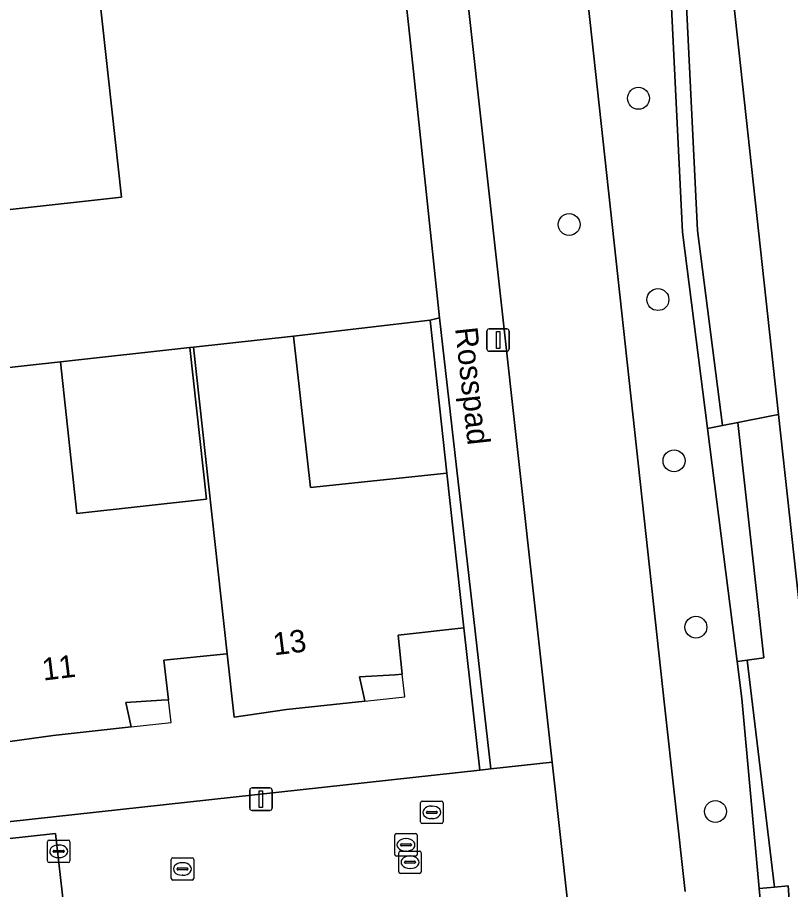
# Model space of a CAD drawing. Extents: x 161248 to 161848, y 384871 to 385383.
# Drawn here: x 161394.3 to 161428.75, y 385160.46 to 385199.35 of the extents above; entities that cross this region are included whole.
import ezdxf

# ---------------------------------------------------------------- set-up
doc = ezdxf.new("R2010")
doc.units = 0
for name, color, linetype in [('IMGEO_Boom', 7, 'Continuous'), ('IMGEO_Erf', 7, 'Continuous'), ('IMGEO_Groenvoorziening', 7, 'Continuous'), ('IMGEO_Hek', 7, 'Continuous'), ('IMGEO_Kolk', 7, 'Continuous'), ('IMGEO_Lichtmast', 7, 'Continuous'), ('IMGEO_Muur', 7, 'Continuous'), ('IMGEO_Openbare_ruimte_label', 7, 'Continuous'), ('IMGEO_Pand', 7, 'Continuous'), ('IMGEO_Pand_nummerreeks', 7, 'Continuous'), ('IMGEO_Pand_overbouw', 7, 'Continuous'), ('IMGEO_Rijbaan_lokaal_open', 7, 'Continuous'), ('IMGEO_Rioolput', 7, 'Continuous'), ('IMGEO_Voetpad_gesloten', 7, 'Continuous'), ('IMGEO_Voetpad_open', 7, 'Continuous')]:
    doc.layers.add(name, color=color, linetype=linetype)

msp = doc.modelspace()

# ---------------------------------------------------------------- linework, layer by layer
at = {"layer": 'IMGEO_Boom'}
for centre in [(161421.968, 385195.743), (161418.879, 385190.113), (161422.835, 385186.767), (161423.555, 385179.578), (161424.528, 385172.161), (161425.399, 385163.944)]:
    msp.add_circle(centre, 0.489, dxfattribs=at)
at = {"layer": 'IMGEO_Erf'}
for points in [[(161391.744, 385183.5), (161396.212, 385183.986), (161401.98, 385184.625), (161402.139, 385184.643), (161406.592, 385185.134), (161412.682, 385185.849), (161413.106, 385185.96), (161411.781, 385198.48), (161406.165, 385250), (161400.82, 385299.379)], [(161389.489, 385206.312), (161397.217, 385207.042), (161398.94, 385191.336), (161393.97, 385190.79)], [(161341.751, 385157.774), (161414.901, 385165.791), (161414.193, 385172.128), (161411.258, 385171.8), (161411.446, 385170.059), (161411.127, 385170.038), (161409.532, 385169.942), (161409.773, 385168.87), (161409.775, 385168.859), (161406.289, 385168.487), (161403.948, 385168.141), (161403.638, 385170.967), (161403.479, 385170.951), (161400.824, 385170.684), (161401.024, 385168.918), (161400.714, 385168.901), (161399.123, 385168.803), (161399.358, 385167.712), (161395.885, 385167.336), (161393.526, 385167.003)]]:
    msp.add_lwpolyline(points, dxfattribs=at)
for points in [[(161413.425, 385179.033), (161412.682, 385185.849), (161406.592, 385185.134), (161407.352, 385178.387)], [(161401.98, 385184.625), (161396.212, 385183.986), (161396.948, 385177.226), (161402.725, 385177.866)]]:
    msp.add_lwpolyline(points, close=True, dxfattribs=at)
at = {"layer": 'IMGEO_Groenvoorziening'}
for points in [[(161410.885, 385280.109), (161414.256, 385250), (161418.32, 385212.789), (161419.633, 385200.77), (161423.135, 385168.705), (161424.044, 385160.38)], [(161428.423, 385148.652), (161427.348, 385160.513), (161426.581, 385168.985), (161426.371, 385170.626), (161425.044, 385181.025), (161423.927, 385189.776), (161423.301, 385202.539), (161422.5, 385209.799), (161420.12, 385231.368), (161419.414, 385237.765), (161418.8, 385243.335), (161418.558, 385245.528), (161418.304, 385247.831), (161417.932, 385251.204), (161416.631, 385262.992), (161416.555, 385263.685), (161415.768, 385270.902)], [(161424.044, 385160.38), (161423.135, 385168.705), (161419.633, 385200.77), (161414.353, 385200.201), (161418.12, 385166.146), (161426.978, 385086.052)]]:
    msp.add_lwpolyline(points, dxfattribs=at)
for points in [[(161422.5, 385209.799), (161423.301, 385202.539), (161423.927, 385189.776), (161425.044, 385181.025), (161425.711, 385181.155), (161424.602, 385189.844), (161423.976, 385202.607), (161423.18, 385209.868)], [(161426.369, 385198.57), (161425.115, 385210.061), (161424.841, 385210.036), (161423.691, 385209.92), (161423.18, 385209.868), (161423.976, 385202.607), (161424.602, 385189.844), (161425.711, 385181.155), (161426.394, 385181.289), (161427.894, 385181.581), (161428.216, 385181.647)], [(161428.216, 385181.647), (161427.894, 385181.581), (161426.394, 385181.289), (161427.562, 385170.797), (161426.819, 385170.69), (161428.029, 385160.572), (161428.642, 385160.625), (161429.639, 385147.11), (161428.645, 385146.959), (161429.316, 385141.851), (161430.492, 385141.951), (161432.485, 385123.048), (161434.155, 385123.24), (161434.587, 385123.289)], [(161425.044, 385181.025), (161426.371, 385170.626), (161426.819, 385170.69), (161427.562, 385170.797), (161426.394, 385181.289), (161425.711, 385181.155)], [(161428.029, 385160.572), (161426.819, 385170.69), (161426.371, 385170.626), (161426.581, 385168.985), (161427.348, 385160.513)], [(161427.348, 385160.513), (161428.423, 385148.652), (161428.645, 385146.959), (161429.639, 385147.11), (161428.642, 385160.625), (161428.029, 385160.572)]]:
    msp.add_lwpolyline(points, close=True, dxfattribs=at)
at = {"layer": 'IMGEO_Hek'}
for points in [[(161423.135, 385168.705), (161419.633, 385200.77)], [(161424.044, 385160.38), (161423.135, 385168.705)]]:
    msp.add_lwpolyline(points, dxfattribs=at)
at = {"layer": 'IMGEO_Kolk'}
for p, q in [((161411.108, 385162.028), (161411.108, 385162.88)), ((161411.183, 385162.954), (161412.035, 385162.954)), ((161411.596, 385162.734), (161411.621, 385162.734)), ((161412.109, 385162.88), (161412.109, 385162.028)), ((161411.367, 385162.448), (161411.367, 385162.46)), ((161411.805, 385162.411), (161411.407, 385162.411)), ((161411.41, 385162.497), (161411.808, 385162.497)), ((161411.851, 385162.46), (161411.851, 385162.448)), ((161401.223, 385161.881), (161402.075, 385161.881)), ((161412.035, 385161.954), (161411.183, 385161.954)), ((161411.619, 385162.174), (161411.594, 385162.174)), ((161401.148, 385160.955), (161401.148, 385161.807)), ((161401.636, 385161.661), (161401.661, 385161.661)), ((161402.149, 385161.807), (161402.149, 385160.955)), ((161401.407, 385161.375), (161401.407, 385161.387)), ((161401.845, 385161.338), (161401.447, 385161.338)), ((161401.45, 385161.424), (161401.848, 385161.424)), ((161401.891, 385161.387), (161401.891, 385161.375)), ((161402.075, 385160.881), (161401.223, 385160.881)), ((161401.659, 385161.101), (161401.634, 385161.101))]:
    msp.add_line(p, q, dxfattribs=at)
for points in [[(161411.108, 385162.028), (161411.108, 385162.88)], [(161411.183, 385162.954), (161412.035, 385162.954)], [(161412.109, 385162.88), (161412.109, 385162.028)], [(161401.223, 385161.881), (161402.075, 385161.881)], [(161412.035, 385161.954), (161411.183, 385161.954)], [(161401.148, 385160.955), (161401.148, 385161.807)], [(161402.149, 385161.807), (161402.149, 385160.955)], [(161402.075, 385160.881), (161401.223, 385160.881)]]:
    msp.add_lwpolyline(points, dxfattribs=at)
for centre, radius, start, end in [((161411.185, 385162.878), 0.0765, 91.552, 178.448), ((161411.185, 385162.878), 0.0765, 91.552, 178.448), ((161412.033, 385162.878), 0.0765, 1.552, 88.448), ((161412.033, 385162.878), 0.0765, 1.552, 88.448), ((161411.407, 385162.457), 0.0403, 85.8775, 175.7526), ((161411.404, 385162.447), 0.0366, 178.938, 274.7102), ((161411.808, 385162.454), 0.043, 264.8664, 352.4533), ((161411.812, 385162.459), 0.0386, 1.7309, 96.639), ((161401.225, 385161.805), 0.0765, 91.552, 178.448), ((161401.225, 385161.805), 0.0765, 91.552, 178.448), ((161402.073, 385161.805), 0.0765, 1.552, 88.448), ((161402.073, 385161.805), 0.0765, 1.552, 88.448), ((161411.185, 385162.03), 0.0765, 181.552, 268.448), ((161411.185, 385162.03), 0.0765, 181.552, 268.448), ((161412.033, 385162.03), 0.0765, 271.552, 358.448), ((161412.033, 385162.03), 0.0765, 271.552, 358.448), ((161401.447, 385161.384), 0.0403, 85.8775, 175.7526), ((161401.444, 385161.374), 0.0366, 178.938, 274.7102), ((161401.848, 385161.381), 0.043, 264.8664, 352.4533), ((161401.852, 385161.386), 0.0386, 1.7309, 96.639), ((161401.225, 385160.957), 0.0765, 181.552, 268.448), ((161401.225, 385160.957), 0.0765, 181.552, 268.448), ((161402.073, 385160.957), 0.0765, 271.552, 358.448), ((161402.073, 385160.957), 0.0765, 271.552, 358.448)]:
    msp.add_arc(centre, radius, start, end, dxfattribs=at)
for centre, major_axis, ratio, start_param, end_param in [((161411.595, 385162.454), (-0.387, 0.002), 0.722429, 4.712389, 7.853982), ((161411.62, 385162.454), (-0.39, 0.002), 0.717154, 1.570796, 4.712389), ((161401.635, 385161.381), (-0.387, 0.002), 0.722429, 4.712389, 7.853982), ((161401.66, 385161.381), (-0.39, 0.002), 0.717154, 1.570796, 4.712389)]:
    msp.add_ellipse(centre, major_axis=major_axis, ratio=ratio, start_param=start_param, end_param=end_param, dxfattribs=at)
at = {"layer": 'IMGEO_Lichtmast'}
for p, q in [((161415.217, 385184.563), (161415.217, 385185.363)), ((161415.217, 385185.363), (161415.217, 385184.563)), ((161415.317, 385185.463), (161416.107, 385185.463)), ((161416.107, 385185.463), (161415.317, 385185.463)), ((161416.207, 385185.363), (161416.207, 385184.563)), ((161416.207, 385184.563), (161416.207, 385185.363)), ((161416.107, 385184.463), (161415.317, 385184.463)), ((161415.317, 385184.463), (161416.107, 385184.463)), ((161404.75, 385164.992), (161405.54, 385164.992)), ((161405.54, 385164.992), (161404.75, 385164.992)), ((161404.65, 385164.092), (161404.65, 385164.892)), ((161404.65, 385164.892), (161404.65, 385164.092)), ((161405.64, 385164.892), (161405.64, 385164.092)), ((161405.64, 385164.092), (161405.64, 385164.892)), ((161405.54, 385163.992), (161404.75, 385163.992)), ((161404.75, 385163.992), (161405.54, 385163.992))]:
    msp.add_line(p, q, dxfattribs=at)
for points in [[(161415.637, 385185.338), (161415.787, 385185.338), (161415.787, 385184.588), (161415.637, 385184.588), (161415.637, 385185.338)], [(161405.07, 385164.867), (161405.22, 385164.867), (161405.22, 385164.117), (161405.07, 385164.117), (161405.07, 385164.867)]]:
    msp.add_lwpolyline(points, dxfattribs=at)
for centre, start, end in [((161415.317, 385185.363), 90, 180), ((161415.317, 385185.363), 90, 180), ((161416.107, 385185.363), 0, 90), ((161416.107, 385185.363), 360, 90), ((161415.317, 385184.563), 180, 270), ((161415.317, 385184.563), 180, 270), ((161416.107, 385184.563), 270, 0), ((161416.107, 385184.563), 270, 0), ((161404.75, 385164.892), 90, 180), ((161404.75, 385164.892), 90, 180), ((161405.54, 385164.892), 0, 90), ((161405.54, 385164.892), 360, 90), ((161404.75, 385164.092), 180, 270), ((161404.75, 385164.092), 180, 270), ((161405.54, 385164.092), 270, 0), ((161405.54, 385164.092), 270, 0)]:
    msp.add_arc(centre, 0.1, start, end, dxfattribs=at)
at = {"layer": 'IMGEO_Muur'}
msp.add_lwpolyline([(161415.386, 385165.844), (161413.106, 385185.96), (161412.682, 385185.849), (161413.425, 385179.033), (161414.193, 385172.128), (161414.901, 385165.791)], close=True, dxfattribs=at)
at = {"layer": 'IMGEO_Pand'}
msp.add_lwpolyline([(161393.97, 385190.79), (161398.94, 385191.336), (161397.217, 385207.042), (161389.489, 385206.312)], dxfattribs=at)
for points in [[(161413.425, 385179.033), (161407.352, 385178.387), (161406.592, 385185.134), (161402.139, 385184.643), (161403.638, 385170.967), (161403.948, 385168.141), (161406.289, 385168.487), (161409.775, 385168.859), (161409.773, 385168.87), (161409.532, 385169.942), (161411.127, 385170.038), (161411.446, 385170.059), (161411.258, 385171.8), (161414.193, 385172.128)], [(161402.139, 385184.643), (161401.98, 385184.625), (161402.725, 385177.866), (161396.948, 385177.226), (161396.212, 385183.986), (161391.744, 385183.5), (161392.474, 385176.74), (161393.22, 385169.836), (161393.526, 385167.003), (161395.885, 385167.336), (161399.358, 385167.712), (161399.123, 385168.803), (161400.714, 385168.901), (161401.024, 385168.918), (161400.824, 385170.684), (161403.479, 385170.951), (161403.638, 385170.967)]]:
    msp.add_lwpolyline(points, close=True, dxfattribs=at)
at = {"layer": 'IMGEO_Pand_overbouw'}
for points in [[(161411.446, 385170.059), (161411.127, 385170.038), (161409.532, 385169.941), (161409.775, 385168.859), (161411.555, 385169.049)], [(161401.024, 385168.918), (161400.714, 385168.901), (161399.123, 385168.803), (161399.358, 385167.712), (161401.139, 385167.905)]]:
    msp.add_lwpolyline(points, close=True, dxfattribs=at)
at = {"layer": 'IMGEO_Rijbaan_lokaal_open'}
msp.add_lwpolyline([(161396.733, 385156.417), (161395.989, 385162.959), (161342.455, 385157.097)], dxfattribs=at)
at = {"layer": 'IMGEO_Rioolput'}
for p, q in [((161412.26, 385163.477), (161412.26, 385164.329)), ((161412.335, 385164.403), (161413.187, 385164.403)), ((161413.261, 385164.329), (161413.261, 385163.477)), ((161412.519, 385163.897), (161412.519, 385163.909)), ((161412.957, 385163.86), (161412.559, 385163.86)), ((161412.562, 385163.946), (161412.96, 385163.946)), ((161412.748, 385164.183), (161412.773, 385164.183)), ((161413.003, 385163.909), (161413.003, 385163.897)), ((161412.771, 385163.623), (161412.746, 385163.623)), ((161413.187, 385163.403), (161412.335, 385163.403)), ((161395.709, 385162.667), (161396.561, 385162.667)), ((161395.634, 385161.741), (161395.634, 385162.593)), ((161396.122, 385162.447), (161396.147, 385162.447)), ((161396.635, 385162.593), (161396.635, 385161.741)), ((161395.893, 385162.161), (161395.893, 385162.173)), ((161396.331, 385162.124), (161395.933, 385162.124)), ((161395.936, 385162.21), (161396.334, 385162.21)), ((161396.145, 385161.887), (161396.12, 385161.887)), ((161396.377, 385162.173), (161396.377, 385162.161)), ((161411.288, 385161.254), (161411.288, 385162.106)), ((161411.363, 385162.18), (161412.215, 385162.18)), ((161411.776, 385161.96), (161411.801, 385161.96)), ((161412.289, 385162.106), (161412.289, 385161.254)), ((161396.561, 385161.667), (161395.709, 385161.667)), ((161411.547, 385161.674), (161411.547, 385161.686)), ((161411.985, 385161.637), (161411.587, 385161.637)), ((161411.59, 385161.723), (161411.988, 385161.723)), ((161412.031, 385161.686), (161412.031, 385161.674)), ((161412.215, 385161.18), (161411.363, 385161.18)), ((161411.799, 385161.4), (161411.774, 385161.4))]:
    msp.add_line(p, q, dxfattribs=at)
for points in [[(161412.26, 385163.477), (161412.26, 385164.329)], [(161412.335, 385164.403), (161413.187, 385164.403)], [(161413.261, 385164.329), (161413.261, 385163.477)], [(161413.187, 385163.403), (161412.335, 385163.403)], [(161395.709, 385162.667), (161396.561, 385162.667)], [(161395.634, 385161.741), (161395.634, 385162.593)], [(161396.635, 385162.593), (161396.635, 385161.741)], [(161411.288, 385161.254), (161411.288, 385162.106)], [(161411.363, 385162.18), (161412.215, 385162.18)], [(161412.289, 385162.106), (161412.289, 385161.254)], [(161396.561, 385161.667), (161395.709, 385161.667)], [(161412.215, 385161.18), (161411.363, 385161.18)]]:
    msp.add_lwpolyline(points, dxfattribs=at)
for centre, radius, start, end in [((161412.337, 385164.327), 0.0765, 91.552, 178.448), ((161412.337, 385164.327), 0.0765, 91.552, 178.448), ((161413.185, 385164.327), 0.0765, 1.552, 88.448), ((161413.185, 385164.327), 0.0765, 1.552, 88.448), ((161412.559, 385163.906), 0.0403, 85.8775, 175.7526), ((161412.556, 385163.896), 0.0366, 178.938, 274.7102), ((161412.96, 385163.903), 0.043, 264.8664, 352.4533), ((161412.964, 385163.908), 0.0386, 1.7309, 96.639), ((161412.337, 385163.479), 0.0765, 181.552, 268.448), ((161412.337, 385163.479), 0.0765, 181.552, 268.448), ((161413.185, 385163.479), 0.0765, 271.552, 358.448), ((161413.185, 385163.479), 0.0765, 271.552, 358.448), ((161395.711, 385162.591), 0.0765, 91.552, 178.448), ((161395.711, 385162.591), 0.0765, 91.552, 178.448), ((161396.559, 385162.591), 0.0765, 1.552, 88.448), ((161396.559, 385162.591), 0.0765, 1.552, 88.448), ((161395.933, 385162.17), 0.0403, 85.8775, 175.7526), ((161395.93, 385162.16), 0.0366, 178.938, 274.7102), ((161396.334, 385162.167), 0.043, 264.8664, 352.4533), ((161396.338, 385162.172), 0.0386, 1.7309, 96.639), ((161411.365, 385162.104), 0.0765, 91.552, 178.448), ((161411.365, 385162.104), 0.0765, 91.552, 178.448), ((161412.213, 385162.104), 0.0765, 1.552, 88.448), ((161412.213, 385162.104), 0.0765, 1.552, 88.448), ((161395.711, 385161.743), 0.0765, 181.552, 268.448), ((161395.711, 385161.743), 0.0765, 181.552, 268.448), ((161396.559, 385161.743), 0.0765, 271.552, 358.448), ((161396.559, 385161.743), 0.0765, 271.552, 358.448), ((161411.587, 385161.683), 0.0403, 85.8775, 175.7526), ((161411.584, 385161.673), 0.0366, 178.938, 274.7102), ((161411.988, 385161.68), 0.043, 264.8664, 352.4533), ((161411.992, 385161.685), 0.0386, 1.7309, 96.639), ((161411.365, 385161.256), 0.0765, 181.552, 268.448), ((161411.365, 385161.256), 0.0765, 181.552, 268.448), ((161412.213, 385161.256), 0.0765, 271.552, 358.448), ((161412.213, 385161.256), 0.0765, 271.552, 358.448)]:
    msp.add_arc(centre, radius, start, end, dxfattribs=at)
for centre, major_axis, ratio, start_param, end_param in [((161412.747, 385163.903), (-0.387, 0.002), 0.722429, 4.712389, 7.853982), ((161412.772, 385163.903), (-0.39, 0.002), 0.717154, 1.570796, 4.712389), ((161396.121, 385162.167), (-0.387, 0.002), 0.722429, 4.712389, 7.853982), ((161396.146, 385162.167), (-0.39, 0.002), 0.717154, 1.570796, 4.712389), ((161411.775, 385161.68), (-0.387, 0.002), 0.722429, 4.712389, 7.853982), ((161411.8, 385161.68), (-0.39, 0.002), 0.717154, 1.570796, 4.712389)]:
    msp.add_ellipse(centre, major_axis=major_axis, ratio=ratio, start_param=start_param, end_param=end_param, dxfattribs=at)
at = {"layer": 'IMGEO_Voetpad_gesloten'}
msp.add_lwpolyline([(161417.881, 385276.364), (161418.44, 385271.231), (161418.959, 385266.457), (161419.237, 385263.908), (161420.964, 385248.092), (161421.223, 385245.715), (161422.767, 385231.573), (161425.115, 385210.061), (161426.369, 385198.57), (161428.216, 385181.647), (161434.587, 385123.289), (161437.317, 385098.274), (161437.566, 385096.339), (161437.632, 385095.831), (161438.183, 385093.977), (161438.834, 385093.495), (161439.577, 385093.264), (161440.609, 385093.05), (161441.669, 385092.83), (161442.358, 385092.869), (161464.945, 385095.485), (161477.693, 385096.962)], dxfattribs=at)
at = {"layer": 'IMGEO_Voetpad_open'}
msp.add_lwpolyline([(161403.458, 385299.646), (161400.82, 385299.379), (161406.165, 385250), (161411.781, 385198.48), (161413.106, 385185.96), (161415.386, 385165.844), (161418.12, 385166.146), (161414.353, 385200.201), (161414.19, 385201.677), (161413.061, 385212.221), (161409.014, 385250)], close=True, dxfattribs=at)
for points in [[(161426.978, 385086.052), (161418.12, 385166.146), (161415.386, 385165.844), (161414.901, 385165.791), (161341.751, 385157.774)], [(161342.455, 385157.097), (161395.989, 385162.959), (161396.733, 385156.417)]]:
    msp.add_lwpolyline(points, dxfattribs=at)

# ---------------------------------------------------------------- texts
at = {"layer": 'IMGEO_Openbare_ruimte_label'}
msp.add_text('Rosspad', height=1, rotation=276.201, dxfattribs=at).set_placement((161413.796, 385185.49))
at = {"layer": 'IMGEO_Pand_nummerreeks'}
for s, rotation, p in [('13', 7.0073, (161405.739, 385170.903)), ('11', 6.9213, (161395.451, 385169.776))]:
    msp.add_text(s, height=1, rotation=rotation, dxfattribs=at).set_placement(p)

doc.saveas('drawing.dxf')
